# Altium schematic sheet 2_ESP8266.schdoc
size 152 x 175 mm
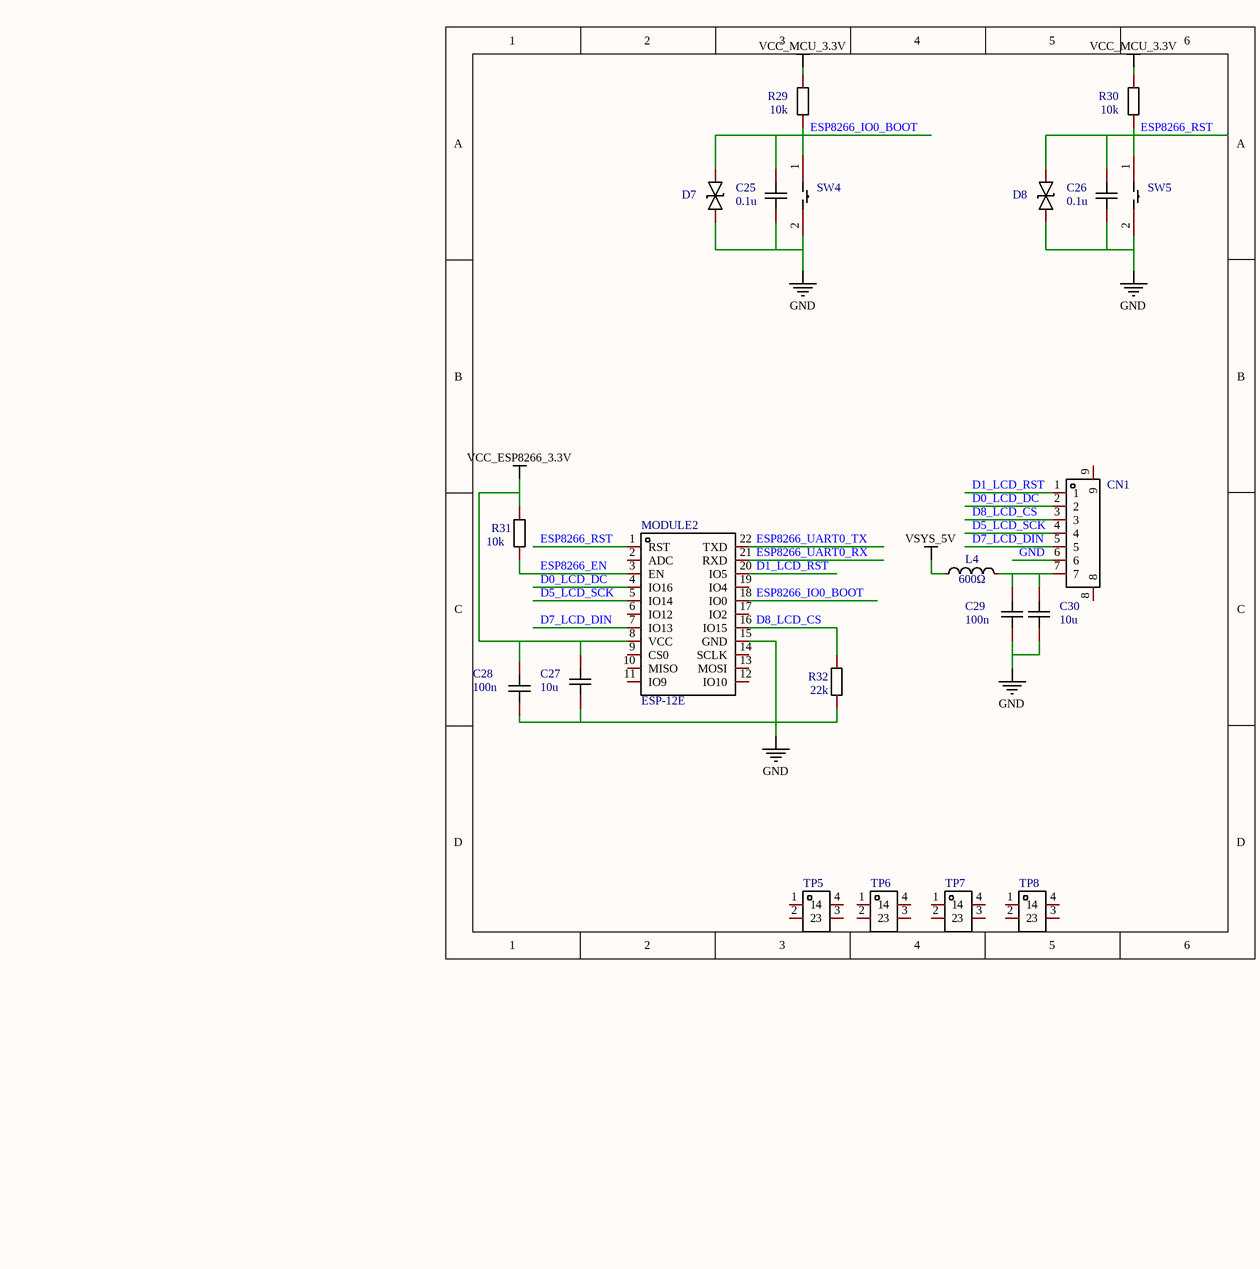
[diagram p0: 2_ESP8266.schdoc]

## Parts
C25  0.1u  [C0603]
C26  0.1u  [C0603]
C27  10u  [C0603]
C28  100n  [C0603]
C29  100n  [C0603]
C30  10u  [C0603]
CN1  X8821WRS-07-9TSN  [CONN-SMD_X8821WRS-07-9TSN]  (value not drawn)
D7  SD03C  [SOD-323_L1.8-W1.3-LS2.5-BI]  (value not drawn)
D8  SD03C  [SOD-323_L1.8-W1.3-LS2.5-BI]  (value not drawn)
L4  600Ω  [L0603]
MODULE2  ESP-12E  [WIFIM-SMD_ESP-12E-BR]
R29  10k  [R0603]
R30  10k  [R0603]
R31  10k  [R0603]
R32  22k  [R0603]
SW4  YTSA010A0252501B  [SW-SMD_L4.0-W3.0-LS5.0]  (value not drawn)
SW5  YTSA010A0252501B  [SW-SMD_L4.0-W3.0-LS5.0]  (value not drawn)
TP5  SMTSO3040MTJ  [SMD_BD5.6-D4.1]  (value not drawn)
TP6  SMTSO3040MTJ  [SMD_BD5.6-D4.1]  (value not drawn)
TP7  SMTSO3040MTJ  [SMD_BD5.6-D4.1]  (value not drawn)
TP8  SMTSO3040MTJ  [SMD_BD5.6-D4.1]  (value not drawn)

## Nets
GND: C25.1 C26.1 C27.1 C28.1 C29.1 C30.1 CN1.6 D7.2 D8.2 MODULE2.15(GND) R32.1 SW4.2 SW5.2
VCC_ESP8266_3.3V: C27.2 C28.2 MODULE2.8(VCC) R31.2
VCC_MCU_3.3V: R29.2 R30.2
VSYS_5V: L4.1
D0_LCD_DC: CN1.2 MODULE2.4(IO16)
D1_LCD_RST: CN1.1 MODULE2.20(IO5)
D5_LCD_SCK: CN1.4 MODULE2.5(IO14)
D7_LCD_DIN: CN1.5 MODULE2.7(IO13)
D8_LCD_CS: CN1.3 MODULE2.16(IO15) R32.2
ESP8266_EN: MODULE2.3(EN) R31.1
ESP8266_IO0_BOOT: C25.2 D7.1 MODULE2.18(IO0) R29.1 SW4.1
ESP8266_RST: C26.2 D8.1 MODULE2.1(RST) R30.1 SW5.1
ESP8266_UART0_RX: MODULE2.21(RXD)
ESP8266_UART0_TX: MODULE2.22(TXD)
NetC29_2: C29.2 C30.2 CN1.7 L4.2

Not connected (* = marked no-connect by the designer): CN1 8 9; MODULE2 2(ADC) 6(IO12) 9(CS0) 10(MISO) 11(IO9) 12(IO10) 13(MOSI) 14(SCLK) 17(IO2) 19(IO4); TP5 1 2 3 4; TP6 1 2 3 4; TP7 1 2 3 4; TP8 1 2 3 4

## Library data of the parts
C25-C30 = CAP_0603: Symbol: CapAcitance; Convert to PCB: yes
CN1 = X8821WRS-07-9TSN: 参考系列:-;间距:2.5mm;插针结构:1x7P;排数:1;每排PIN数:7;行距:-;公母:公型插针;安装方式:卧贴;额定电流:3A;触头材质:黄铜;触头镀层:锡;工作温度范围:-25℃~+85℃;焊接温度(最大值):260℃;; Manufacturer: XKB Connectivity(中国星坤); Add into BOM: yes; Pitch: 2.5mm; Pins Structure: 1x7P; Number of PINs Per Row: 7; Gender: 公型插针; Current Rating (Max): 3A; Welding Temperature (Max): 260℃
D7 D8 = SD03C_C502532: 极性:双向;反向截止电压(Vrwm):3.3V;击穿电压(最小值):4V;峰值脉冲电流(Ipp)@10/1000μs:20A;最大钳位电压:16V;; Manufacturer: MDD; Add into BOM: yes; Polarity: 双向; Reverse Stand-Off Voltage (Vrwm): 3.3V; Breakdown Voltage (Min): 4V; Peak Pulse Current (Ipp)@10/1000μs: 20A; Maximum Clamping Voltage: 16V
L4 = L_0603: Symbol: SDFL1608S100KTF; Add into BOM: yes
MODULE2 = ESP-12E_C89297: 频率:2.4GHz;发射功率:16dBm;核心处理器:ESP32;天线形式:PCB 板载天线;接收灵敏度:-90dBm;; Manufacturer: Ai-Thinker(安信可); Add into BOM: yes; Output Power: 16dBm; Core Processor: ESP32; Support Interface: GPIO；UART；IIC；PWM；SPI；ADC; Wireless Standard: 802.11b/g/n; Operating Voltage: 3V~3.6V; Receive  Current: 56mA; Send  Current: 170mA; Sensitivity: -90dBm
R29-R31 = AECR0603F1K50K9: Manufacturer: RESI(开步睿思）; Add into BOM: yes; Tolerance: ±1%; Power(Watts): 100mW; Temperature Coefficient: ±100ppm/℃; Overload Voltage (Max): 50V; Description: 电阻类型:厚膜电阻;阻值:1.5kΩ;精度:±1%;功率:100mW;温度系数:±100ppm/℃;最大工作电压:50V;工作温度范围:-55℃~+125℃;
R32 = AECR0603F1K50K9: Manufacturer: RESI(开步睿思）; Add into BOM: yes; Value: 10k; Tolerance: ±1%; Power(Watts): 100mW; Temperature Coefficient: ±100ppm/℃; Overload Voltage (Max): 50V; Description: 电阻类型:厚膜电阻;阻值:1.5kΩ;精度:±1%;功率:100mW;温度系数:±100ppm/℃;最大工作电压:50V;工作温度范围:-55℃~+125℃;
SW4 SW5 = YTSA010A0252501B: 触点电流:50mA;额定电压(DC):12V;绝缘电阻:100MΩ;电路结构:单刀单掷;安装方式:立贴;按钮形状:圆形按钮;按钮/盖帽颜色:黑色;作用力:250gf;机械寿命:50000;引脚样式:SMD接片;开关长度:4mm;开关宽度:3mm;开关高度:2.5mm;带支架:否;; Manufacturer: DGBZ(东莞博众); Add into BOM: yes; Contact Current: 50mA; Voltage Rating (DC): 12V; Insulation Resistance: 100MΩ; Circuit: 单刀单掷; Actuator Style: 圆形按钮; Actuator/Cap Color: 黑色; Operating Force: 250gf; Mechanical Life: 50000; Pin Style: SMD接片; Switch Length: 4mm; Switch Width: 3mm; Switch Height: 2.5mm; Strike Gundam: 否
TP5-TP8 = SMTSO3040MTJ: 螺母类型:电路板表贴圆螺母柱;螺纹规格:M3;螺距(牙数):0.5;级别(材质):铁;表面处理:镀锡;执行标准:-;; Manufacturer: Sinhoo(雄和远景); Add into BOM: yes; Thread Specification: M3; Pitch of Thread: 0.5; Finish: 镀锡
